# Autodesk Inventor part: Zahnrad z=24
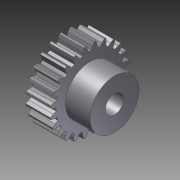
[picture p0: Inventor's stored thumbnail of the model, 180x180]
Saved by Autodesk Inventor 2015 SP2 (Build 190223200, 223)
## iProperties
Created: 2012-07
Part Number: Zahnrad z=24
Material: Stahl
Document SubType Name: Modeling
Designer: rYan
Mass: 4.63809 g
Surface Area: 6.6827 cm^2
Volume: 0.59084 cm^3
Density: 7.85 g/cm^3
Appearance: Platte
Übersetzungsnorm: STEP AP214IS
Dateiname: c:/PPEXPORT/antriebselemente_und_normteile/stirnzahnraeder/stirnzahnraeder_stahl/modul_05_und_07/artikel_nr___21102400.stp
Postprozessor: Build: 138, Release: 2013 RTM - Date: Thu 03/01/2012
Gesendete Einheiten: Millimeter
Unbestimmtheit: 1.0000000000000002e-06
Author: rYan
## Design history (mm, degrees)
node "11"
node "1"
node "Basis1"
